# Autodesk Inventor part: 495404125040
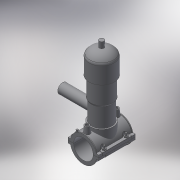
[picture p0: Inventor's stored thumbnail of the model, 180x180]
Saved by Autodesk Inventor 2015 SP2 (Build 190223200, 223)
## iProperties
Created: 2017-07
Part Number: 495404125040
Material: Generic
Description: PLASSON TAPPING VALVE 125-40
Document SubType Name: Modeling
Designer: KIM
Density: 1 g/cm^3
Appearance: Default
Author: KIM
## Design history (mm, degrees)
derived "495404-4954S4.ipt"
feature "Solid1::495404-4954S4.ipt"
feature "Solid2::495404-4954S4.ipt"
tag "TaggingFeature1"
body "Solid1"
body "Solid2"
other parameters: "d0" = 125, "d2" = 162, "d3" = 31.25, "d4" = 118, "d5" = 0, "d6" = 0.1, "d8" = 0, "d19" = 6, "d20" = 6, "d21" = 70.8, "d23" = 0, "d24" = 35.4, "d26" = 0, "d27" = 3, "d28" = 3, "d29" = 3, "d30" = 41.66667, "d31" = 6, "d32" = 0, "d33" = 0, "d34" = 0.6, "d40" = 81.25, "d47" = 124.125, "d70" = 15, "d72" = 0, "d73" = 6, "d75" = 5, "d76" = 0, "d77" = 6.25, "d78" = 92.5, "d79" = 15, "d80" = 47.2, "d82" = 5 deg, "d84" = 4, "d85" = 14, "d86" = 0, "d87" = 3, "d88" = 0, "d89" = 1, "d90" = 1, "d91" = 94.4, "d92" = 0, "d93" = 0.5, "d94" = 65.78947, "d96" = 160.9375, "d97" = 2.36, "d98" = 0, "d120" = 140 deg, "d121" = 24.228, "d122" = 20 deg, "d123" = 312.5, "d124" = 93.75, "d126" = 0, "d143" = 128.75, "d145" = 24.03846, "d149" = 1.875, "d150" = 26.44231, "d153" = 118, "d154" = 0, "d156" = 78.125, "d157" = 160 deg, "d159" = 6.25, "d161" = 1.875, "d162" = 70.8, "d163" = 0, "d164" = 62.5, "d167" = 12.5, "d168" = 76.21951, "d170" = 3, "d172" = 0, "d173" = 1, "d175" = 62.5, "d176" = 20 deg, "d177" = 8.75, "d178" = 31.25, "d180" = 0, "d183" = 12.5, "d184" = 7, "d185" = 38.35, "d186" = 38.35, "d187" = 78.125, "d188" = 9.375, "d189" = 8.75, "d190" = 0, "d191" = 117.1875, "d193" = 6.8, "d194" = 2.95, "d195" = 90 deg, "d197" = 0, "d199" = 0, "d205" = 14.64, "d206" = 81.33333, "d207" = 244, "d208" = 224.48, "d209" = 207.4, "d210" = 200.08, "d211" = 146.4, "d212" = 85.4, "d213" = 65.88, "d214" = 73.2, "d216" = 19.52, "d217" = 70.76, "d218" = 80.52, "d220" = 125, "d222" = 0, "d223" = 156.25, "d224" = 137, "d225" = 46, "d229" = 137, "d230" = 0, "d_" = 125, "B_" = 162, "H_" = 137, "L_" = 118, "d_t" = 6, "H_1" = 46, "H_2" = 244, "d148" = 1.875, "d160" = 1.875, "d169" = 3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
